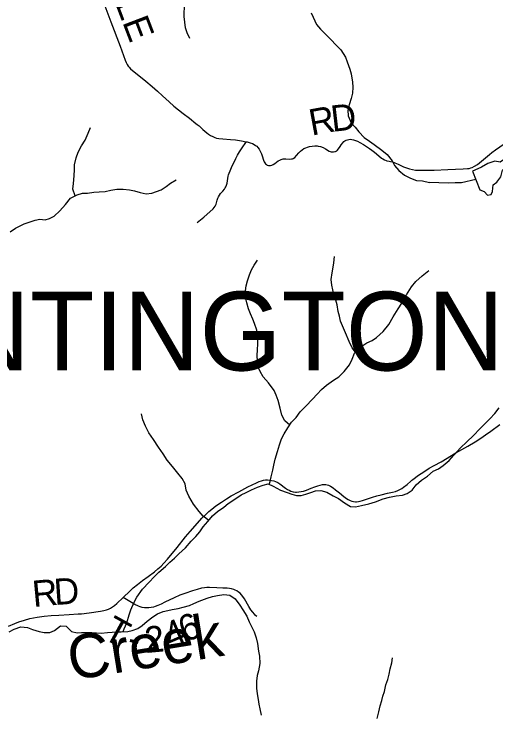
# Model space of a CAD drawing. Extents: x 1451455 to 1749751, y 218250 to 574981.
# Drawn here: x 1607183 to 1612692, y 263241 to 271255 of the extents above; entities that cross this region are included whole.
import ezdxf

# ---------------------------------------------------------------- set-up
doc = ezdxf.new("R2010")
doc.units = 0
for name, color, linetype in [('GM_X_County_Road', 7, 'Continuous'), ('GM_X_County_Road_Text', 7, 'Continuous'), ('GM_X_Minor_Lake', 7, 'Continuous'), ('GM_X_Minor_River', 7, 'Continuous'), ('GM_X_Minor_River_Text', 7, 'Continuous'), ('GM_X_Township_Road', 7, 'Continuous'), ('GM_X_Township_Road_Text', 7, 'Continuous'), ('GM_X_Township_ROW', 7, 'Continuous'), ('GM_X_Township_Text', 7, 'Continuous')]:
    doc.layers.add(name, color=color, linetype=linetype)

msp = doc.modelspace()

# ---------------------------------------------------------------- linework, layer by layer
at = {"layer": 'GM_X_County_Road'}
for points in [[(1608186.4, 271443.3), (1608291.2, 271164.1), (1608396, 270888.7), (1608455.3, 270726.6), (1608466.4, 270699.6), (1608476.5, 270679.5), (1608488.3, 270660.5), (1608499.9, 270645.5), (1608515, 270629), (1608538.9, 270607.3), (1608610.9, 270551.7), (1608690.4, 270488.2), (1608763.3, 270426.9), (1608824.6, 270372.2), (1608882.1, 270318.3), (1608957, 270249.7), (1609011.6, 270202.8), (1609116.4, 270118.9), (1609188.3, 270062.4), (1609263.2, 270004), (1609278.6, 269991.7), (1609298.8, 269974.9), (1609342.9, 269935.5), (1609386.3, 269896), (1609406.6, 269880.1), (1609428.2, 269866.2), (1609453.9, 269852.8), (1609477.7, 269843.1), (1609499.3, 269836.9), (1609524.6, 269832), (1609569.9, 269826.6), (1609658.2, 269819.7), (1609713.9, 269815.1), (1609782.5, 269806.6), (1609838.1, 269795.4)], [(1609838.1, 269795.4), (1609849.2, 269793.2), (1609884, 269782.6), (1609909, 269773), (1609926.9, 269763.8), (1609943.9, 269752.9), (1609957, 269742.3), (1609971, 269727.6), (1609984.7, 269708.6), (1609997.7, 269685.6), (1610011.6, 269655.5), (1610019.9, 269633.8), (1610035.2, 269583.6), (1610042.6, 269566), (1610048.7, 269555.1), (1610058.6, 269543), (1610070.3, 269533.2), (1610078, 269528.6), (1610092.4, 269523.5), (1610107.5, 269522.2), (1610116.4, 269522.9), (1610128.6, 269525.5), (1610145.6, 269533.1), (1610164.2, 269545.3), (1610203.9, 269574.9), (1610221.1, 269585.5), (1610236.1, 269592.9), (1610259.1, 269599.1), (1610289.6, 269600), (1610335.3, 269596.5), (1610354.3, 269597.8), (1610366, 269601), (1610374.8, 269604.3), (1610392.8, 269615.7), (1610412.3, 269636), (1610439, 269669.7), (1610457.7, 269688.8), (1610475.9, 269703.5), (1610495.8, 269716), (1610517.3, 269725.7), (1610539.5, 269733.3), (1610562.1, 269738.9), (1610591.7, 269744), (1610621.5, 269746.8), (1610648.3, 269746.8), (1610661.6, 269745.7), (1610688, 269740.8), (1610716.3, 269730.5), (1610745.4, 269713.8), (1610783.7, 269688.7), (1610798.2, 269682.5), (1610809.6, 269679), (1610825.2, 269677.9), (1610834.1, 269678.3), (1610849.3, 269681.7), (1610857.8, 269684.7), (1610871.3, 269692.1), (1610876.6, 269695.6), (1610894, 269713.2), (1610911.9, 269740), (1610924.3, 269759.8), (1610940, 269781.7), (1610954.4, 269796), (1610965.5, 269804.1), (1610980.4, 269812.3), (1610996.5, 269818.2), (1611009.8, 269821.2), (1611026.8, 269822.6), (1611043.7, 269821.3), (1611063.8, 269817.5), (1611086.2, 269810.3), (1611107.6, 269800.7), (1611134.2, 269786.9), (1611176.6, 269761.7), (1611245.7, 269717.3), (1611272.6, 269698.2), (1611304, 269674.3), (1611354.3, 269632), (1611384.5, 269607.3), (1611397.8, 269598.4), (1611417.5, 269588), (1611435.3, 269580.9), (1611444.5, 269578.3), (1611469.9, 269573.4), (1611486.1, 269570.6), (1611508.2, 269564), (1611536.4, 269554.6), (1611573.1, 269539), (1611635.2, 269509.4), (1611671.2, 269494.6), (1611702, 269484.6), (1611736.7, 269476.6), (1611771.9, 269471.2), (1611810.7, 269468.3), (1611869.3, 269467.8), (1611987.2, 269471.4), (1612141, 269478.5), (1612229.6, 269482.3), (1612317.7, 269484.4), (1612366.4, 269487.4), (1612385.5, 269489.9), (1612403.8, 269494.5), (1612421.6, 269501.3), (1612447.1, 269514.7), (1612479.3, 269536.3), (1612525.9, 269572), (1612618.4, 269650.6), (1612644.2, 269671), (1612686.7, 269702.1), (1612835.7, 269803.5)], [(1608429, 264583.2), (1608506.2, 264658.1), (1608545.5, 264692.8), (1608593.2, 264732.9), (1608650.3, 264777), (1608716.4, 264825.4), (1608789.1, 264879.4), (1608828.9, 264911.6), (1608864.7, 264943.7), (1608896.8, 264975.9), (1608937.3, 265021), (1609047.7, 265156.7), (1609143.1, 265277.2), (1609195.5, 265340), (1609280.3, 265435.5), (1609331.7, 265490.5), (1609375.3, 265534.8), (1609411.6, 265568.1), (1609444.4, 265595.2), (1609491.5, 265631), (1609553.1, 265674.5), (1609613.6, 265713.9), (1609667, 265746), (1609753, 265793.9), (1609857.5, 265848.6), (1609954.3, 265895.9), (1609987.2, 265910.1), (1610011.7, 265918.7), (1610033.9, 265924), (1610058.1, 265927.8), (1610080.8, 265928.4), (1610103.8, 265926.8), (1610126.5, 265923.2), (1610151.9, 265916.6), (1610173.5, 265908.9), (1610197.3, 265897.8), (1610222.4, 265882.3), (1610285.4, 265835), (1610310.2, 265818.9), (1610327.5, 265809.6), (1610348.5, 265800.5), (1610373.6, 265793), (1610399.5, 265789.4), (1610412.5, 265788.7), (1610438.6, 265790.3), (1610464.4, 265794.5), (1610493, 265801.6), (1610527.3, 265812.9), (1610578.9, 265833.9), (1610621.5, 265850.9), (1610655.6, 265862.4), (1610684.1, 265869.8), (1610710, 265874.3), (1610729.3, 265875.8), (1610747.6, 265875.3), (1610763.6, 265872.1), (1610779.1, 265866.7), (1610802.7, 265855.1), (1610830.5, 265837.8), (1610859.6, 265816.4), (1610902.7, 265781), (1610953, 265738.8), (1610982, 265717.3), (1611004.2, 265703.3), (1611024.8, 265692.9), (1611046.3, 265684.8), (1611065.1, 265679.9), (1611087.9, 265677.4), (1611097.7, 265677.2), (1611120.5, 265679.9), (1611139.7, 265684.3), (1611167.8, 265693.6), (1611214.1, 265710.1), (1611279.4, 265731.9), (1611329.7, 265746.7), (1611380.5, 265759.4), (1611454.1, 265775.7), (1611508.5, 265787.9), (1611543.2, 265797.7), (1611571, 265807.7), (1611591.9, 265817.1), (1611614.9, 265829.6), (1611636.8, 265844), (1611675.6, 265874.2), (1611719.2, 265914), (1611732.1, 265924.1), (1611742.2, 265932.5), (1611808.1, 265981.3), (1611867.5, 266022.3), (1611927.6, 266061.8), (1611984.4, 266093.7), (1612065.1, 266137), (1612085.3, 266147.9), (1612116.6, 266165.9), (1612235, 266236.3), (1612372.1, 266313.5), (1612456.2, 266364.7), (1612519.5, 266405.7), (1612573.6, 266442.7), (1612632, 266484.4), (1612736.8, 266561.7)], [(1607119, 264256), (1607194.3, 264288.7), (1607240, 264306.5), (1607302.5, 264326.5), (1607362.5, 264343.1), (1607404, 264352.6), (1607445.9, 264359.9), (1607527.2, 264370.1), (1607608.8, 264377.3), (1607693.9, 264382.2), (1607811.8, 264388.9), (1607916.3, 264396.4), (1607955.4, 264399.2), (1608043.2, 264409.7), (1608173, 264428.2), (1608211.6, 264435.5), (1608240.2, 264443.1), (1608264.8, 264452.1), (1608285.5, 264461.9), (1608310.7, 264477.3), (1608331.9, 264492.8), (1608359.2, 264516.3), (1608429, 264583.2)]]:
    msp.add_lwpolyline(points, dxfattribs=at)
at = {"layer": 'GM_X_Minor_Lake'}
for points in [[(1612508.4, 269243), (1612558.2, 269226.3), (1612595.7, 269183.8), (1612635.9, 269191.3), (1612654.4, 269227.1), (1612659.4, 269303.2), (1612703.8, 269332.7), (1612748.7, 269394.2), (1612765.7, 269470.2), (1612814.4, 269519.6), (1612834.9, 269553.4), (1612819.4, 269595.7), (1612789.4, 269596.1), (1612738.9, 269560.7), (1612681, 269571.4), (1612598.5, 269544.4), (1612527.9, 269503.2), (1612485.6, 269483.8), (1612425.1, 269456.5)], [(1612425.1, 269456.5), (1612508.4, 269243)]]:
    msp.add_lwpolyline(points, dxfattribs=at)
at = {"layer": 'GM_X_Minor_River'}
for points in [[(1609193.7, 270976.6), (1609160.6, 271041.3), (1609143.4, 271097.7), (1609136.3, 271160), (1609129.3, 271228.3), (1609131.4, 271372.6)], [(1610581.4, 271267.5), (1610602.6, 271217.1), (1610641.5, 271136.3), (1610686.8, 271081.5), (1610736.1, 271030.6), (1610805.2, 270963.4), (1610866.3, 270898.4), (1610917.6, 270845.5), (1610970.4, 270762.5), (1610991.7, 270708), (1611022.5, 270625.3), (1611037.7, 270571), (1611050.4, 270476.5), (1611055.5, 270418.2), (1611050.5, 270350.1), (1611037.6, 270290.1), (1611014.6, 270216.3), (1610999.6, 270154.3), (1611002.7, 270092.1), (1611037.6, 270011.3), (1611080.9, 269960.6), (1611126.2, 269907.8), (1611187.3, 269844.7), (1611246.8, 269801.7), (1611300.3, 269762.8), (1611387.4, 269699.4), (1611448.7, 269648.4), (1611503.8, 269575.4), (1611531, 269522.8), (1611580.2, 269466), (1611647.5, 269412.8), (1611715.1, 269379.8), (1611782.8, 269350.7), (1611852.8, 269347.7), (1611930.9, 269328.5)], [(1607880.7, 269175.5), (1607855.3, 269252.8), (1607862.2, 269316.9), (1607869.5, 269405.1), (1607874.6, 269477.2), (1607875.4, 269531.3), (1607892.5, 269611.3), (1607917.5, 269677.2), (1607954.6, 269748.8), (1607995.6, 269812.4), (1608030.8, 269892.2), (1608055.7, 269958)], [(1607137.4, 268763.7), (1607200.1, 268806.9), (1607299, 268855.7), (1607355.3, 268876.9), (1607423.7, 268898), (1607477.9, 268909.2), (1607537.8, 268900.4), (1607590.1, 268915.6), (1607642.6, 268945), (1607707.6, 269006.2), (1607772.7, 269077.5), (1607829.8, 269150.9), (1607906.4, 269187.9), (1607966.7, 269207.1), (1608024.8, 269208.3), (1608095, 269219.3), (1608157.1, 269220.4), (1608225.3, 269225.4), (1608291.6, 269240.5), (1608357.8, 269251.6), (1608431.9, 269252.5), (1608503.8, 269243.5), (1608561.7, 269232.6), (1608625.6, 269215.7), (1608693.4, 269200.6), (1608759.5, 269205.7), (1608864.2, 269244.3), (1608920.8, 269283.6), (1608971.4, 269321), (1609038.1, 269360.2)], [(1612462, 269361.9), (1612297.3, 269325.8), (1612225.2, 269324.8), (1612147, 269319.7), (1611930.9, 269328.5)], [(1611087.5, 267390.7), (1611048.2, 267437.7), (1611015.3, 267510.4), (1610972.7, 267609.3), (1610949.4, 267663.8), (1610914.6, 267744.5), (1610905.3, 267798.8), (1610890.1, 267855.2), (1610875.2, 267929.6), (1610860, 267984), (1610842.7, 268034.4), (1610825.6, 268100.8), (1610814.4, 268153.1), (1610809.4, 268221.4), (1610818.5, 268297.5), (1610831.4, 268361.5), (1610838.2, 268411.6), (1610845.2, 268481.7)], [(1610334.2, 266554.6), (1610279.3, 266602.3), (1610246.2, 266667), (1610225.4, 266749.5), (1610202.6, 266836.1), (1610181.5, 266898.6), (1610158.2, 266949.1), (1610093.5, 267038.3), (1610032.4, 267107.4), (1609997.2, 267166), (1609973.9, 267216.5), (1609966.9, 267284.8), (1609963.8, 267349), (1609964.8, 267417.2), (1609969.8, 267483.3), (1609970.9, 267557.5), (1609960.1, 267641.9), (1609933.1, 267716.5), (1609911.8, 267767), (1609884.7, 267825.6), (1609863.5, 267886), (1609844.5, 267952.5), (1609829.4, 268018.9), (1609828.4, 268089.1), (1609835.3, 268147.2), (1609850.2, 268205.1), (1609875.2, 268273), (1609898, 268330.8), (1609928.8, 268382.5), (1609967.7, 268440.1)], [(1610100.1, 265876.8), (1610111.1, 265908.8), (1610123.9, 265962.7), (1610141, 266038.7), (1610151.9, 266098.7), (1610166.9, 266166.7), (1610194.2, 266252.6), (1610219.3, 266330.4), (1610242.3, 266396.3), (1610271.2, 266456), (1610314.2, 266523.6), (1610355.2, 266587.2), (1610408, 266642.6), (1610453, 266706.2), (1610520, 266771.4), (1610593.3, 266850.6), (1610648.2, 266910), (1610697, 266963.4), (1610755.8, 267012.7), (1610834.7, 267067.7), (1610895.3, 267107), (1610958.2, 267168.2), (1611017.4, 267243.6), (1611048.3, 267307.3), (1611075.4, 267379.2), (1611158.7, 267458.2), (1611217.3, 267495.5), (1611275.7, 267522.7), (1611328.3, 267556.1), (1611401.3, 267625.2), (1611466.6, 267706.5), (1611517.9, 267794), (1611575.3, 267883.5), (1611614.3, 267949.1), (1611667.7, 268044.6), (1611727.1, 268134), (1611778, 268195.5), (1611849, 268260.6), (1611924, 268323.7)], [(1611907.9, 265973.1), (1611973.1, 266027.7), (1612033.5, 266057), (1612090.1, 266094.3), (1612156.9, 266151.6), (1612209.8, 266211.1), (1612287, 266294.2), (1612360, 266363.4), (1612437, 266436.6), (1612506.1, 266511.9), (1612623.8, 266626.6), (1612678.6, 266688), (1612729.6, 266753.5)], [(1609409.2, 265463.7), (1609346.6, 265514.6), (1609299.3, 265565.4), (1609234.4, 265650.6), (1609181.7, 265741.6), (1609152.7, 265812.2), (1609137.7, 265882.7), (1609106.5, 265943.3), (1609057.4, 266004.2), (1608994.4, 266081.3), (1608935.4, 266152.3), (1608886.4, 266225.3), (1608833.5, 266304.2), (1608778.7, 266389.3), (1608725.7, 266466.3), (1608684.8, 266543.1), (1608655.8, 266613.7), (1608640.8, 266682.1)], [(1608430.8, 264193.9), (1608440.9, 264225.9), (1608472, 264295.7), (1608499.3, 264387.5), (1608518.1, 264441.4), (1608557.5, 264531.1), (1608588.3, 264586.8), (1608653.7, 264680.1), (1608729, 264759.3), (1608785.9, 264818.6), (1608838.7, 264872), (1608913.7, 264937.2), (1608964.5, 264986.6), (1609017.2, 265031.9), (1609066, 265083.4), (1609143.1, 265152.5), (1609208.3, 265227.8), (1609261.1, 265281.2), (1609305.9, 265334.7), (1609346.8, 265390.2), (1609399.7, 265451.7), (1609452.7, 265519.1), (1609507.5, 265568.4), (1609580.3, 265617.5), (1609631, 265658.9), (1609697.6, 265700.1), (1609780.5, 265757.1), (1609835, 265786.4), (1609899.5, 265815.5), (1609966, 265846.7), (1610032.4, 265869.8), (1610086.7, 265883), (1610144.4, 265856.1), (1610229.8, 265812.8), (1610305.5, 265783.6), (1610357.2, 265764.8), (1610411.1, 265752), (1610465.2, 265751.2), (1610517.4, 265766.5), (1610575.7, 265783.7), (1610630.1, 265803), (1610690.2, 265808.2), (1610760, 265789.1), (1610829.5, 265746), (1610891.1, 265717), (1610962.4, 265665.8), (1611029.9, 265624.8), (1611085.9, 265619.9), (1611154.2, 265635), (1611238.6, 265655.8), (1611317, 265678.8), (1611401.6, 265713.7), (1611473.9, 265732.7), (1611550.2, 265745.6), (1611622.4, 265754.6), (1611676.7, 265771.9), (1611733.3, 265811.2), (1611780.2, 265870.7), (1611839.1, 265926), (1611907.9, 265973.1)], [(1607127.1, 264192.7), (1607185.6, 264221.9), (1607260, 264248.9), (1607338, 264239.8), (1607395.7, 264216.9), (1607469.4, 264193.8), (1607527.3, 264182.9), (1607593.4, 264184), (1607647.8, 264207.2), (1607714.6, 264258.4), (1607780.7, 264255.5), (1607841.9, 264196.4), (1607903.7, 264181.5), (1607955.8, 264182.7), (1608019.9, 264185.8), (1608071.9, 264183.1), (1608179.9, 264177.5), (1608252.1, 264182.5), (1608304.2, 264187.8), (1608356.3, 264191), (1608406.4, 264192.3), (1608482.5, 264197.2), (1608534.7, 264206.5), (1608599.1, 264229.6), (1608649.7, 264263), (1608704.4, 264312.4), (1608769.2, 264361.6), (1608823.8, 264396.9), (1608888.3, 264424), (1608940.5, 264435.3), (1608990.7, 264446.6), (1609060.9, 264459.7), (1609117.2, 264472.9), (1609187.6, 264494), (1609240, 264517.3), (1609300.4, 264542.5), (1609391, 264577.3), (1609451.3, 264594.5), (1609507.6, 264607.7), (1609581.8, 264618.6), (1609651.8, 264611.6), (1609711.2, 264570.6), (1609764.2, 264497.7), (1609799.5, 264443), (1609844.5, 264372.2), (1609871.6, 264307.6), (1609900.7, 264245), (1609928, 264192.5), (1609953, 264121.9), (1609966, 264057.5), (1609978.8, 263969.1)], [(1609978.8, 263969.1), (1609988, 263914.8), (1609994.8, 263830.5), (1609977.5, 263746.5), (1609960.7, 263692.5), (1609955.8, 263626.4), (1609954.6, 263548.2), (1609961.7, 263483.9), (1609974.8, 263417.6), (1609982, 263365.3), (1609993.2, 263311), (1610008.2, 263240.6)], [(1611333, 263199.4), (1611352.1, 263275.4), (1611369.2, 263345.3), (1611386, 263405.3), (1611400.8, 263457.2), (1611417.6, 263511.1), (1611434.7, 263585.1), (1611455.6, 263647), (1611472.5, 263706.9), (1611483.4, 263766.9), (1611500.5, 263838.9), (1611509.3, 263894.9)]]:
    msp.add_lwpolyline(points, dxfattribs=at)
at = {"layer": 'GM_X_Township_Road'}
msp.add_lwpolyline([(1609959.8, 264365.4), (1609944.9, 264378.1), (1609930.8, 264391.9), (1609912.3, 264414.8), (1609891.2, 264444.1), (1609866.8, 264482.9), (1609818.2, 264568.5), (1609799.9, 264595.7), (1609783.3, 264616), (1609767.1, 264632.3), (1609749.3, 264646.8), (1609730.2, 264659.6), (1609712.9, 264668.8), (1609694.7, 264676.3), (1609669.5, 264683.6), (1609646.9, 264687.8), (1609620.8, 264690.3), (1609568.3, 264691.1), (1609499.8, 264694.5), (1609418.1, 264698.9), (1609385.4, 264698.4), (1609359.3, 264696), (1609327.3, 264689.4), (1609276.7, 264676.6), (1609223.4, 264660.3), (1609136.3, 264631.1), (1609077.9, 264609.3), (1609012.2, 264579.6), (1608909, 264529.4), (1608864.6, 264508.2), (1608828.6, 264492.2), (1608798, 264480.5), (1608775.9, 264474.3), (1608750.3, 264468.7), (1608724.2, 264465.5), (1608701.3, 264465), (1608675.1, 264466.3), (1608649.1, 264470), (1608626.9, 264475.7), (1608605.8, 264484.4), (1608565.1, 264505.3), (1608506.4, 264540.2), (1608429, 264583.2)], dxfattribs=at)
at = {"layer": 'GM_X_Township_ROW'}
msp.add_lwpolyline([(1609277.4, 268872.9), (1609296.1, 268886.3), (1609354.4, 268931.9), (1609459.5, 269029.4), (1609469.6, 269041.4), (1609481.8, 269059.5), (1609493.4, 269081.8), (1609498.4, 269096), (1609506, 269125.3), (1609513.1, 269150.5), (1609519.5, 269165.5), (1609531.2, 269185.2), (1609544.7, 269203.7), (1609568.6, 269230.8), (1609588, 269253), (1609597.5, 269266.4), (1609605.4, 269280.7), (1609612.4, 269299.1), (1609617.9, 269321.3), (1609626.5, 269373.1), (1609632.3, 269402.1), (1609636.6, 269417.8), (1609642.5, 269436.5), (1609652.2, 269460.7), (1609670.6, 269499.1), (1609718.7, 269603.1), (1609738.3, 269640.9), (1609760.2, 269677.5), (1609797.8, 269735.2), (1609825, 269775.8), (1609838.1, 269795.4)], dxfattribs=at)

# ---------------------------------------------------------------- texts
at = {"layer": 'GM_X_County_Road_Text'}
for s, rotation, p in [('L', 290.78617, (1608339.2, 271373.8)), ('E', 290.89284, (1608419, 271163.4)), ('R', 10.44055, (1610585.1, 269863.4)), ('D', 6.54756, (1610822.1, 269907.3)), ('R', 5.29911, (1607405.2, 264474.8)), ('D', 3.89446, (1607648.6, 264497.4))]:
    msp.add_text(s, height=300, rotation=rotation, dxfattribs=at).set_placement(p)
at = {"layer": 'GM_X_Minor_River_Text'}
msp.add_text('Creek', height=499.99, rotation=9.21893, dxfattribs=at).set_placement((1607838.8, 263635))
at = {"layer": 'GM_X_Township_Road_Text'}
for s, rotation, p in [('T', 331.06247, (1608184.4, 264124.8)), ('6', 23.5612, (1609143.4, 264065)), ('4', 23.40376, (1608973, 263991.3)), ('2', 5.28874, (1608689.2, 263948.7)), ('-', 346.84256, (1608464.6, 263984))]:
    msp.add_text(s, height=300, rotation=rotation, dxfattribs=at).set_placement(p)
at = {"layer": 'GM_X_Township_Text'}
msp.add_text('HUNTINGTON', height=900, rotation=0.00001, dxfattribs=at).set_placement((1604758.8, 267179.7))

doc.saveas('drawing.dxf')
